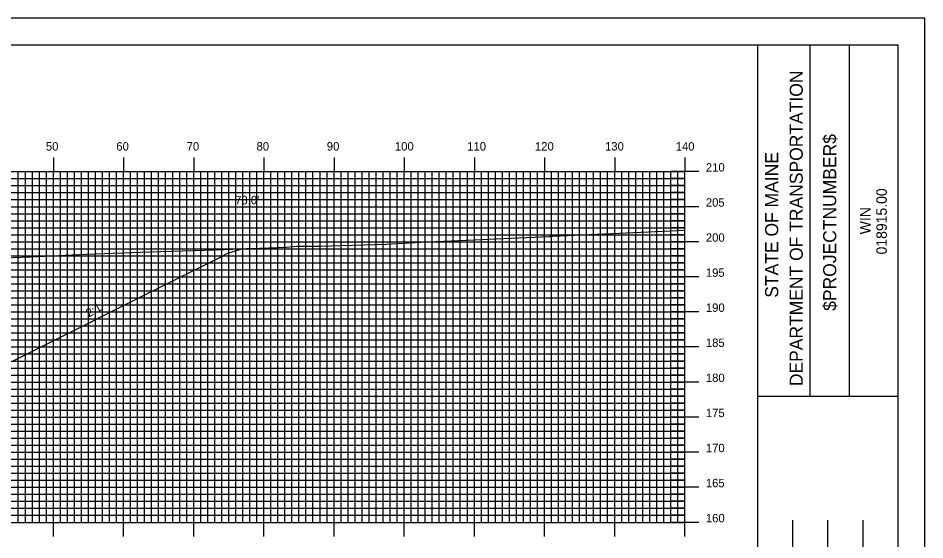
# Model space of a CAD drawing. Extents: x 1794453 to 1794796, y 442591 to 442811.
# Drawn here: x 1794663.3 to 1794792.6, y 442736.2 to 442810.5 of the extents above; entities that cross this region are included whole.
import ezdxf

# ---------------------------------------------------------------- set-up
doc = ezdxf.new("R2010")
doc.units = 0
for name, color, linetype in [('ANNOTATION', 7, 'Continuous'), ('BORDER', 7, 'Continuous'), ('D_Roadway_Centerline', 7, 'Continuous'), ('D_Roadway_SlopeLines', 7, 'Continuous'), ('D_Text_Standard', 7, 'Continuous'), ('H_V ANNOTATION', 7, 'Continuous'), ('MAJOR', 7, 'Continuous'), ('MINOR', 7, 'Continuous'), ('PLOT BOUNDARY', 7, 'Continuous'), ('S_Roadway_Centerline', 7, 'Continuous')]:
    doc.layers.add(name, color=color, linetype=linetype)

msp = doc.modelspace()

# ---------------------------------------------------------------- linework, layer by layer
at = {"layer": 'BORDER'}
for p, q in [((1794768.74, 442596.67), (1794768.74, 442806.67)), ((1794776.2, 442756.66), (1794776.2, 442806.66)), ((1794781.79, 442756.66), (1794781.79, 442806.66)), ((1794768.74, 442756.65), (1794788.74, 442756.65)), ((1794773.74, 442721.67), (1794773.74, 442738.97)), ((1794778.74, 442721.67), (1794778.74, 442738.97)), ((1794783.74, 442721.67), (1794783.74, 442738.97))]:
    msp.add_line(p, q, dxfattribs=at)
msp.add_lwpolyline([(1794468.74, 442596.67), (1794788.74, 442596.67), (1794788.74, 442806.67), (1794468.74, 442806.67)], close=True, dxfattribs=at)
at = {"layer": 'D_Roadway_Centerline'}
msp.add_arc((1794697.01, 442767.74), 10, 93.8378, 116.5651, dxfattribs=at)
at = {"layer": 'D_Roadway_SlopeLines'}
for p, q in [((1794686.86, 442773.84), (1794692.54, 442776.68)), ((1794662.5, 442761.67), (1794686.86, 442773.84))]:
    msp.add_line(p, q, dxfattribs=at)
at = {"layer": 'MAJOR'}
for p, q in [((1794668.34, 442790.67), (1794668.34, 442788.67)), ((1794678.34, 442790.67), (1794678.34, 442788.67)), ((1794688.34, 442790.67), (1794688.34, 442788.67)), ((1794698.34, 442790.67), (1794698.34, 442788.67)), ((1794708.34, 442790.67), (1794708.34, 442788.67)), ((1794718.34, 442790.67), (1794718.34, 442788.67)), ((1794728.34, 442790.67), (1794728.34, 442788.67)), ((1794738.34, 442790.67), (1794738.34, 442788.67)), ((1794748.34, 442790.67), (1794748.34, 442788.67)), ((1794758.34, 442790.67), (1794758.34, 442788.67)), ((1794478.34, 442788.67), (1794758.34, 442788.67)), ((1794478.34, 442788.67), (1794758.34, 442788.67)), ((1794668.34, 442738.67), (1794668.34, 442788.67)), ((1794678.34, 442738.67), (1794678.34, 442788.67)), ((1794688.34, 442738.67), (1794688.34, 442788.67)), ((1794698.34, 442738.67), (1794698.34, 442788.67)), ((1794708.34, 442738.67), (1794708.34, 442788.67)), ((1794718.34, 442738.67), (1794718.34, 442788.67)), ((1794728.34, 442738.67), (1794728.34, 442788.67)), ((1794738.34, 442738.67), (1794738.34, 442788.67)), ((1794748.34, 442738.67), (1794748.34, 442788.67)), ((1794760.34, 442788.67), (1794756.34, 442788.67)), ((1794758.34, 442738.67), (1794758.34, 442788.67)), ((1794758.34, 442738.67), (1794758.34, 442788.67)), ((1794478.34, 442783.67), (1794758.34, 442783.67)), ((1794760.34, 442783.67), (1794756.34, 442783.67)), ((1794478.34, 442778.67), (1794758.34, 442778.67)), ((1794760.34, 442778.67), (1794756.34, 442778.67)), ((1794478.34, 442773.67), (1794758.34, 442773.67)), ((1794760.34, 442773.67), (1794756.34, 442773.67)), ((1794478.34, 442768.67), (1794758.34, 442768.67)), ((1794760.34, 442768.67), (1794756.34, 442768.67)), ((1794478.34, 442763.67), (1794758.34, 442763.67)), ((1794760.34, 442763.67), (1794756.34, 442763.67)), ((1794478.34, 442758.67), (1794758.34, 442758.67)), ((1794760.34, 442758.67), (1794756.34, 442758.67)), ((1794478.34, 442753.67), (1794758.34, 442753.67)), ((1794760.34, 442753.67), (1794756.34, 442753.67)), ((1794478.34, 442748.67), (1794758.34, 442748.67)), ((1794760.34, 442748.67), (1794756.34, 442748.67)), ((1794478.34, 442743.67), (1794758.34, 442743.67)), ((1794760.34, 442743.67), (1794756.34, 442743.67)), ((1794478.34, 442738.67), (1794758.34, 442738.67)), ((1794478.34, 442738.67), (1794758.34, 442738.67)), ((1794668.34, 442736.66), (1794668.34, 442738.67)), ((1794678.34, 442736.66), (1794678.34, 442738.67)), ((1794688.34, 442736.66), (1794688.34, 442738.67)), ((1794698.34, 442736.66), (1794698.34, 442738.67)), ((1794708.34, 442736.66), (1794708.34, 442738.67)), ((1794718.34, 442736.66), (1794718.34, 442738.67)), ((1794728.34, 442736.66), (1794728.34, 442738.67)), ((1794738.34, 442736.66), (1794738.34, 442738.67)), ((1794748.34, 442736.66), (1794748.34, 442738.67)), ((1794760.34, 442738.67), (1794756.34, 442738.67)), ((1794758.34, 442736.66), (1794758.34, 442738.67))]:
    msp.add_line(p, q, dxfattribs=at)
at = {"layer": 'MINOR'}
for p, q in [((1794663.34, 442738.67), (1794663.34, 442788.67)), ((1794664.34, 442738.67), (1794664.34, 442788.67)), ((1794665.34, 442738.67), (1794665.34, 442788.67)), ((1794666.34, 442738.67), (1794666.34, 442788.67)), ((1794667.34, 442738.67), (1794667.34, 442788.67)), ((1794669.34, 442738.67), (1794669.34, 442788.67)), ((1794670.34, 442738.67), (1794670.34, 442788.67)), ((1794671.34, 442738.67), (1794671.34, 442788.67)), ((1794672.34, 442738.67), (1794672.34, 442788.67)), ((1794673.34, 442738.67), (1794673.34, 442788.67)), ((1794674.34, 442738.67), (1794674.34, 442788.67)), ((1794675.34, 442738.67), (1794675.34, 442788.67)), ((1794676.34, 442738.67), (1794676.34, 442788.67)), ((1794677.34, 442738.67), (1794677.34, 442788.67)), ((1794679.34, 442738.67), (1794679.34, 442788.67)), ((1794680.34, 442738.67), (1794680.34, 442788.67)), ((1794681.34, 442738.67), (1794681.34, 442788.67)), ((1794682.34, 442738.67), (1794682.34, 442788.67)), ((1794683.34, 442738.67), (1794683.34, 442788.67)), ((1794684.34, 442738.67), (1794684.34, 442788.67)), ((1794685.34, 442738.67), (1794685.34, 442788.67)), ((1794686.34, 442738.67), (1794686.34, 442788.67)), ((1794687.34, 442738.67), (1794687.34, 442788.67)), ((1794689.34, 442738.67), (1794689.34, 442788.67)), ((1794690.34, 442738.67), (1794690.34, 442788.67)), ((1794691.34, 442738.67), (1794691.34, 442788.67)), ((1794692.34, 442738.67), (1794692.34, 442788.67)), ((1794693.34, 442738.67), (1794693.34, 442788.67)), ((1794694.34, 442738.67), (1794694.34, 442788.67)), ((1794695.34, 442738.67), (1794695.34, 442788.67)), ((1794696.34, 442738.67), (1794696.34, 442788.67)), ((1794697.34, 442738.67), (1794697.34, 442788.67)), ((1794699.34, 442738.67), (1794699.34, 442788.67)), ((1794700.34, 442738.67), (1794700.34, 442788.67)), ((1794701.34, 442738.67), (1794701.34, 442788.67)), ((1794702.34, 442738.67), (1794702.34, 442788.67)), ((1794703.34, 442738.67), (1794703.34, 442788.67)), ((1794704.34, 442738.67), (1794704.34, 442788.67)), ((1794705.34, 442738.67), (1794705.34, 442788.67)), ((1794706.34, 442738.67), (1794706.34, 442788.67)), ((1794707.34, 442738.67), (1794707.34, 442788.67)), ((1794709.34, 442738.67), (1794709.34, 442788.67)), ((1794710.34, 442738.67), (1794710.34, 442788.67)), ((1794711.34, 442738.67), (1794711.34, 442788.67)), ((1794712.34, 442738.67), (1794712.34, 442788.67)), ((1794713.34, 442738.67), (1794713.34, 442788.67)), ((1794714.34, 442738.67), (1794714.34, 442788.67)), ((1794715.34, 442738.67), (1794715.34, 442788.67)), ((1794716.34, 442738.67), (1794716.34, 442788.67)), ((1794717.34, 442738.67), (1794717.34, 442788.67)), ((1794719.34, 442738.67), (1794719.34, 442788.67)), ((1794720.34, 442738.67), (1794720.34, 442788.67)), ((1794721.34, 442738.67), (1794721.34, 442788.67)), ((1794722.34, 442738.67), (1794722.34, 442788.67)), ((1794723.34, 442738.67), (1794723.34, 442788.67)), ((1794724.34, 442738.67), (1794724.34, 442788.67)), ((1794725.34, 442738.67), (1794725.34, 442788.67)), ((1794726.34, 442738.67), (1794726.34, 442788.67)), ((1794727.34, 442738.67), (1794727.34, 442788.67)), ((1794729.34, 442738.67), (1794729.34, 442788.67)), ((1794730.34, 442738.67), (1794730.34, 442788.67)), ((1794731.34, 442738.67), (1794731.34, 442788.67)), ((1794732.34, 442738.67), (1794732.34, 442788.67)), ((1794733.34, 442738.67), (1794733.34, 442788.67)), ((1794734.34, 442738.67), (1794734.34, 442788.67)), ((1794735.34, 442738.67), (1794735.34, 442788.67)), ((1794736.34, 442738.67), (1794736.34, 442788.67)), ((1794737.34, 442738.67), (1794737.34, 442788.67)), ((1794739.34, 442738.67), (1794739.34, 442788.67)), ((1794740.34, 442738.67), (1794740.34, 442788.67)), ((1794741.34, 442738.67), (1794741.34, 442788.67)), ((1794742.34, 442738.67), (1794742.34, 442788.67)), ((1794743.34, 442738.67), (1794743.34, 442788.67)), ((1794744.34, 442738.67), (1794744.34, 442788.67)), ((1794745.34, 442738.67), (1794745.34, 442788.67)), ((1794746.34, 442738.67), (1794746.34, 442788.67)), ((1794747.34, 442738.67), (1794747.34, 442788.67)), ((1794749.34, 442738.67), (1794749.34, 442788.67)), ((1794750.34, 442738.67), (1794750.34, 442788.67)), ((1794751.34, 442738.67), (1794751.34, 442788.67)), ((1794752.34, 442738.67), (1794752.34, 442788.67)), ((1794753.34, 442738.67), (1794753.34, 442788.67)), ((1794754.34, 442738.67), (1794754.34, 442788.67)), ((1794755.34, 442738.67), (1794755.34, 442788.67)), ((1794756.34, 442738.67), (1794756.34, 442788.67)), ((1794757.34, 442738.67), (1794757.34, 442788.67)), ((1794478.34, 442787.67), (1794758.34, 442787.67)), ((1794758.34, 442787.67), (1794756.34, 442787.67)), ((1794478.34, 442786.67), (1794758.34, 442786.67)), ((1794478.34, 442785.67), (1794758.34, 442785.67)), ((1794758.34, 442786.67), (1794756.34, 442786.67)), ((1794758.34, 442785.67), (1794756.34, 442785.67)), ((1794478.34, 442784.67), (1794758.34, 442784.67)), ((1794758.34, 442784.67), (1794756.34, 442784.67)), ((1794478.34, 442782.67), (1794758.34, 442782.67)), ((1794478.34, 442781.67), (1794758.34, 442781.67)), ((1794758.34, 442782.67), (1794756.34, 442782.67)), ((1794758.34, 442781.67), (1794756.34, 442781.67)), ((1794478.34, 442780.67), (1794758.34, 442780.67)), ((1794758.34, 442780.67), (1794756.34, 442780.67)), ((1794478.34, 442779.67), (1794758.34, 442779.67)), ((1794758.34, 442779.67), (1794756.34, 442779.67)), ((1794478.34, 442777.67), (1794758.34, 442777.67)), ((1794478.34, 442776.67), (1794758.34, 442776.67)), ((1794758.34, 442777.67), (1794756.34, 442777.67)), ((1794758.34, 442776.67), (1794756.34, 442776.67)), ((1794478.34, 442775.67), (1794758.34, 442775.67)), ((1794758.34, 442775.67), (1794756.34, 442775.67)), ((1794478.34, 442774.67), (1794758.34, 442774.67)), ((1794758.34, 442774.67), (1794756.34, 442774.67)), ((1794478.34, 442772.67), (1794758.34, 442772.67)), ((1794758.34, 442772.67), (1794756.34, 442772.67)), ((1794478.34, 442771.67), (1794758.34, 442771.67)), ((1794758.34, 442771.67), (1794756.34, 442771.67)), ((1794478.34, 442770.67), (1794758.34, 442770.67)), ((1794758.34, 442770.67), (1794756.34, 442770.67)), ((1794478.34, 442769.67), (1794758.34, 442769.67)), ((1794758.34, 442769.67), (1794756.34, 442769.67)), ((1794478.34, 442767.67), (1794758.34, 442767.67)), ((1794758.34, 442767.67), (1794756.34, 442767.67)), ((1794478.34, 442766.67), (1794758.34, 442766.67)), ((1794758.34, 442766.67), (1794756.34, 442766.67)), ((1794478.34, 442765.67), (1794758.34, 442765.67)), ((1794758.34, 442765.67), (1794756.34, 442765.67)), ((1794478.34, 442764.67), (1794758.34, 442764.67)), ((1794758.34, 442764.67), (1794756.34, 442764.67)), ((1794478.34, 442762.67), (1794758.34, 442762.67)), ((1794758.34, 442762.67), (1794756.34, 442762.67)), ((1794478.34, 442761.67), (1794758.34, 442761.67)), ((1794758.34, 442761.67), (1794756.34, 442761.67)), ((1794478.34, 442760.67), (1794758.34, 442760.67)), ((1794478.34, 442759.67), (1794758.34, 442759.67)), ((1794758.34, 442760.67), (1794756.34, 442760.67)), ((1794758.34, 442759.67), (1794756.34, 442759.67)), ((1794478.34, 442757.67), (1794758.34, 442757.67)), ((1794758.34, 442757.67), (1794756.34, 442757.67)), ((1794478.34, 442756.67), (1794758.34, 442756.67)), ((1794758.34, 442756.67), (1794756.34, 442756.67)), ((1794478.34, 442755.67), (1794758.34, 442755.67)), ((1794478.34, 442754.67), (1794758.34, 442754.67)), ((1794758.34, 442755.67), (1794756.34, 442755.67)), ((1794758.34, 442754.67), (1794756.34, 442754.67)), ((1794478.34, 442752.67), (1794758.34, 442752.67)), ((1794758.34, 442752.67), (1794756.34, 442752.67)), ((1794478.34, 442751.67), (1794758.34, 442751.67)), ((1794478.34, 442750.67), (1794758.34, 442750.67)), ((1794758.34, 442751.67), (1794756.34, 442751.67)), ((1794758.34, 442750.67), (1794756.34, 442750.67)), ((1794478.34, 442749.67), (1794758.34, 442749.67)), ((1794758.34, 442749.67), (1794756.34, 442749.67)), ((1794478.34, 442747.67), (1794758.34, 442747.67)), ((1794758.34, 442747.67), (1794756.34, 442747.67)), ((1794478.34, 442746.67), (1794758.34, 442746.67)), ((1794478.34, 442745.67), (1794758.34, 442745.67)), ((1794758.34, 442746.67), (1794756.34, 442746.67)), ((1794758.34, 442745.67), (1794756.34, 442745.67)), ((1794478.34, 442744.67), (1794758.34, 442744.67)), ((1794758.34, 442744.67), (1794756.34, 442744.67)), ((1794478.34, 442742.67), (1794758.34, 442742.67)), ((1794478.34, 442741.67), (1794758.34, 442741.67)), ((1794758.34, 442742.67), (1794756.34, 442742.67)), ((1794758.34, 442741.67), (1794756.34, 442741.67)), ((1794478.34, 442740.67), (1794758.34, 442740.67)), ((1794758.34, 442740.67), (1794756.34, 442740.67)), ((1794478.34, 442739.67), (1794758.34, 442739.67)), ((1794758.34, 442739.67), (1794756.34, 442739.67))]:
    msp.add_line(p, q, dxfattribs=at)
at = {"layer": 'PLOT BOUNDARY'}
msp.add_lwpolyline([(1794452.55, 442590.55), (1794792.55, 442590.55), (1794792.55, 442810.55), (1794452.55, 442810.55)], close=True, dxfattribs=at)
at = {"layer": 'S_Roadway_Centerline'}
msp.add_lwpolyline([(1794658.84, 442776.27), (1794665.09, 442776.54), (1794673.01, 442776.9), (1794682.03, 442777.24), (1794691.4, 442777.54), (1794701.58, 442777.9), (1794703.02, 442778.02), (1794706.26, 442778.05), (1794715.73, 442778.32), (1794720.71, 442778.63), (1794739.01, 442779.44), (1794739.15, 442779.44), (1794739.23, 442779.45), (1794739.51, 442779.46), (1794758.34, 442780.34)], dxfattribs=at)

# ---------------------------------------------------------------- texts
at = {"layer": 'ANNOTATION'}
msp.add_text('2:1', height=1.2, rotation=29.7449, dxfattribs=at).set_placement((1794673.4, 442767.86))
msp.add_text('2:1', height=1.2, rotation=29.7449, dxfattribs=at).set_placement((1794673.4, 442767.86))
at = {"layer": 'BORDER'}
for s, height, p in [('DEPARTMENT OF TRANSPORTATION', 1.8635, (1794775.15, 442758.08)), ('$PROJECTNUMBER$', 1.8635, (1794779.92, 442768.82)), ('STATE OF MAINE', 1.8635, (1794771.65, 442770.69)), ('018915.00', 1.491, (1794787.13, 442776.86)), ('WIN', 1.491, (1794784.81, 442779.73))]:
    msp.add_text(s, height=height, rotation=90, dxfattribs=at).set_placement(p)
at = {"layer": 'D_Text_Standard'}
msp.add_text("78.0'", height=1.2, dxfattribs=at).set_placement((1794694.25, 442784.01))
at = {"layer": 'H_V ANNOTATION'}
for s, p in [('50', (1794667.27, 442791.67)), ('60', (1794677.31, 442791.67)), ('70', (1794687.34, 442791.67)), ('80', (1794697.29, 442791.67)), ('90', (1794707.31, 442791.67)), ('100', (1794717.02, 442791.67)), ('110', (1794727.32, 442791.67)), ('120', (1794736.98, 442791.67)), ('130', (1794746.97, 442791.67)), ('140', (1794757.04, 442791.67)), ('210', (1794761.34, 442788.67)), ('205', (1794761.34, 442783.67)), ('200', (1794761.34, 442778.67)), ('195', (1794761.34, 442773.67)), ('190', (1794761.34, 442768.67)), ('185', (1794761.34, 442763.67)), ('180', (1794761.34, 442758.67)), ('175', (1794761.34, 442753.67)), ('170', (1794761.34, 442748.67)), ('165', (1794761.34, 442743.67)), ('160', (1794761.34, 442738.67))]:
    msp.add_text(s, height=1.2, dxfattribs=at).set_placement(p)

doc.saveas('drawing.dxf')
